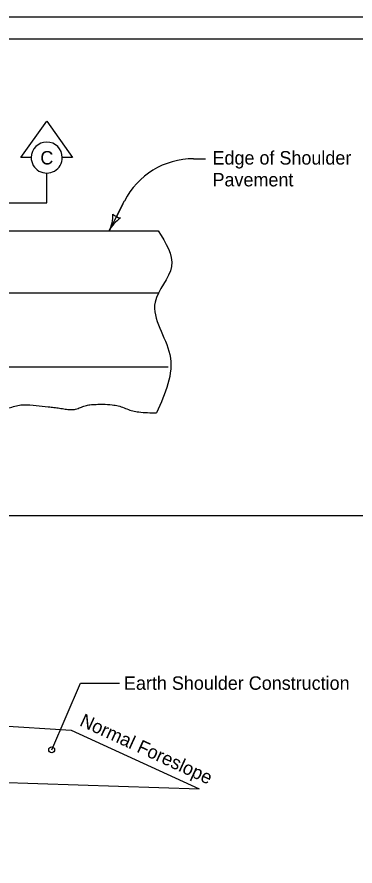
# Model space of a CAD drawing. Extents: x 6410 to 81668, y 3928 to 11667.
# Drawn here: x 11815 to 12218, y 8933 to 9944 of the extents above; entities that cross this region are included whole.
import ezdxf

# ---------------------------------------------------------------- set-up
doc = ezdxf.new("R2010")
doc.units = 0
for name, color, linetype in [('dsnCellElements', 7, 'Continuous'), ('dsnNonPlotable', 7, 'Continuous'), ('dsnStdBlockModified', 7, 'Continuous'), ('Level 10', 7, 'Continuous'), ('Level 11', 7, 'Continuous'), ('Level 14', 7, 'Continuous'), ('Level 8', 7, 'Continuous')]:
    doc.layers.add(name, color=color, linetype=linetype)

msp = doc.modelspace()

# ---------------------------------------------------------------- linework, layer by layer
at = {"layer": 'dsnCellElements'}
for p, q in [((12025.3, 9775.2), (12039.6, 9775.2)), ((11942.9, 9724.8), (11924.7, 9689.2)), ((11856.4, 9071.5), (11890.6, 9150.9)), ((11890.6, 9150.9), (11937, 9150.9))]:
    msp.add_line(p, q, dxfattribs=at)
for centre, radius, start, end in [((12025.3, 9682.8), 92.4, 90, 152.9341), ((11886.9, 9708.5), 42.5, 332.9341, 1.0066), ((11940.9, 9720.9), 16.4, 225.2008, 260.6675), ((11962.6, 9669.8), 42.5, 124.8616, 152.9341)]:
    msp.add_arc(centre, radius, start, end, dxfattribs=at)
at = {"layer": 'dsnNonPlotable'}
msp.add_line((10153.2, 9917.9), (13248.9, 9917.9), dxfattribs=at)
at = {"layer": 'dsnStdBlockModified'}
for p, q in [((11941, 9721), (11924.7, 9689.2)), ((10369.6, 9689.2), (11983.4, 9689.2)), ((10369.9, 9615.5), (11983.7, 9615.5)), ((11744.8, 9103.4), (11879.7, 9095)), ((11879.7, 9095), (12032.2, 9025.1)), ((11548.9, 9040.9), (12032.2, 9025.1))]:
    msp.add_line(p, q, dxfattribs=at)
for points in [[(11983.4, 9689.2), (11999.2, 9647.1), (11979.6, 9604.5), (11997.1, 9542), (11981.3, 9472.7)], [(11701.5, 9476.5), (11703.5, 9476.6), (11711.1, 9477), (11718.7, 9477.7), (11726.2, 9478.5), (11733.8, 9479.4), (11738.5, 9480.4), (11743.2, 9481.9), (11747.9, 9483.2), (11750.2, 9483.7), (11752.6, 9484), (11759.1, 9484), (11765.7, 9483.3), (11772.3, 9482.3), (11778.8, 9481.1), (11782.8, 9480.2), (11786.8, 9479), (11790.8, 9477.9), (11794.8, 9477.1), (11798.3, 9477.1), (11801.9, 9477.6), (11809, 9479.5), (11816.1, 9481.5), (11823.3, 9482.3), (11837.8, 9481.3), (11852.4, 9480), (11859.1, 9479.2), (11865.8, 9478.2), (11872.5, 9477.2), (11879.2, 9476.6), (11884.9, 9477.1), (11890.6, 9479), (11896.3, 9481), (11902, 9482.3), (11909.5, 9482.8), (11917.1, 9482.9), (11928.5, 9482.2), (11932.2, 9481.7), (11939.2, 9479.9), (11946.1, 9477.3), (11953, 9474.9), (11960.1, 9473.7), (11981.3, 9472.7)]]:
    msp.add_spline(points, degree=3, dxfattribs=at)
at = {"layer": 'Level 10'}
for p, q in [((11850.5, 9722.7), (11850.5, 9758.2)), ((11762.4, 9722.7), (11850.5, 9722.7))]:
    msp.add_line(p, q, dxfattribs=at)
msp.add_lwpolyline([(11832.1, 9776.6), (11819.7, 9776.6), (11850.5, 9819.8), (11881.4, 9776.6), (11869, 9776.6)], dxfattribs=at)
for start, end in [(0.0008, 179.9992), (179.9992, 0.0008)]:
    msp.add_arc((11850.5, 9776.6), 18.5, start, end, dxfattribs=at)
at = {"layer": 'Level 11'}
for p, q in [((10353.3, 9527.6), (11995.3, 9527.6)), ((12308.8, 9349.9), (10153.2, 9349.9))]:
    msp.add_line(p, q, dxfattribs=at)
at = {"layer": 'Level 14'}
msp.add_circle((11856.4, 9071.5), 3.54, dxfattribs=at)
at = {"layer": 'Level 8'}
msp.add_lwpolyline([(10132.5, 9944), (13267.5, 9944), (13267.5, 7924), (10132.5, 7924)], close=True, dxfattribs=at)

# ---------------------------------------------------------------- texts
at = {"layer": 'dsnCellElements'}
for s, p in [('Edge of Shoulder', (12048, 9768.3)), ('Pavement', (12048, 9742.3)), ('Earth Shoulder Construction', (11942.5, 9142.9))]:
    msp.add_text(s, height=16, dxfattribs=at).set_placement(p)
msp.add_text('Normal Foreslope', height=16, rotation=335.372, dxfattribs=at).set_placement((11888.6, 9100.7))
at = {"layer": 'Level 10'}
msp.add_text('C', height=16, dxfattribs=at).set_placement((11842.9, 9768.4))

doc.saveas('drawing.dxf')
